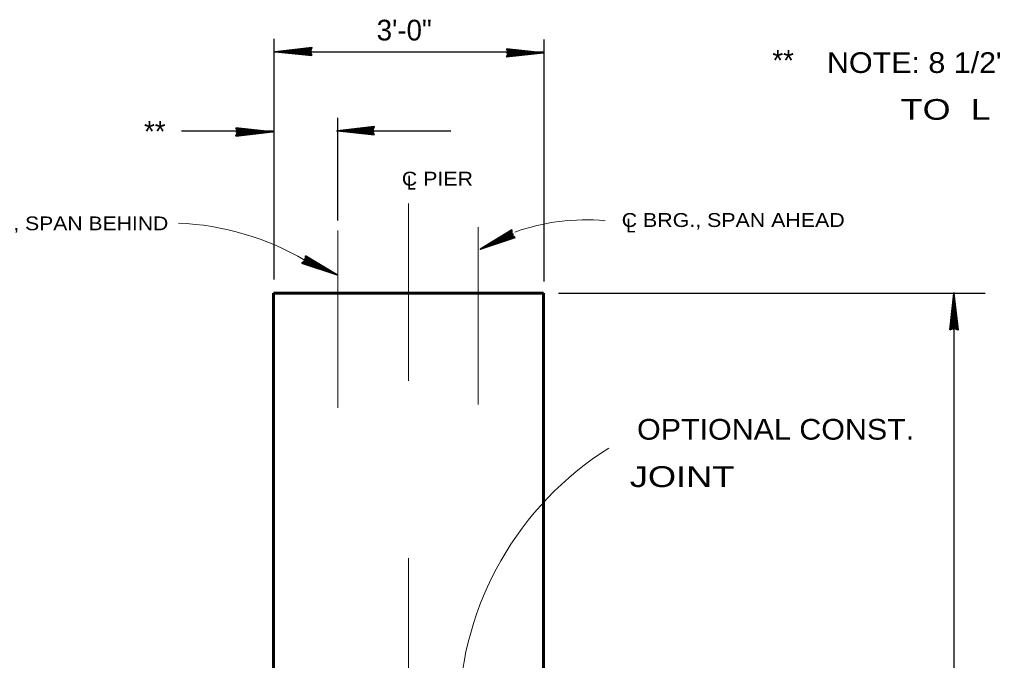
# Model space of a CAD drawing. Extents: x 1.6 to 19.9, y 2.8 to 9.5.
# Drawn here: x 17.696 to 18.245, y 8.128 to 8.49 of the extents above; entities that cross this region are included whole.
import ezdxf
from ezdxf.enums import TextEntityAlignment as Align

# ---------------------------------------------------------------- set-up
doc = ezdxf.new("R2010")
doc.units = 0
doc.header["$LTSCALE"] = 0.0047
doc.linetypes.add('DOT_DASHED', pattern=[7.7, 5, -1.2, 0.3, -1.2])
doc.layers.add('1', color=7, linetype='Continuous', lineweight=35)
doc.layers.add('5', color=7, linetype='Continuous', lineweight=13)

msp = doc.modelspace()

# ---------------------------------------------------------------- linework, layer by layer
at = {"layer": '1', "lineweight": 25}
for p, q in [((17.83975, 8.478833), (17.83975, 8.343)), ((17.992, 8.478333), (17.992, 8.34175)), ((17.839917, 8.4715), (17.991917, 8.4715)), ((17.875667, 8.43425), (17.875667, 8.37625)), ((17.787667, 8.426917), (17.839167, 8.426917)), ((17.875083, 8.426917), (17.939667, 8.426917)), ((18.2235, 8.335667), (18.2235, 7.721417)), ((18.00025, 8.33525), (18.241083, 8.33525))]:
    msp.add_line(p, q, dxfattribs=at)
at = {"layer": '1'}
for p, q in [((17.86075, 8.4735), (17.846417, 8.471917)), ((17.86075, 8.47325), (17.846417, 8.47175)), ((17.860833, 8.473083), (17.846417, 8.4715)), ((17.860833, 8.472833), (17.846417, 8.47125)), ((17.971417, 8.472833), (17.987, 8.471083)), ((17.971417, 8.47275), (17.987, 8.471)), ((17.971417, 8.472667), (17.987, 8.471)), ((17.9715, 8.472917), (17.987, 8.47125)), ((17.861167, 8.4715), (17.8405, 8.4715)), ((17.860833, 8.47), (17.845417, 8.471583)), ((17.86075, 8.46975), (17.845417, 8.471417)), ((17.86075, 8.4695), (17.845417, 8.47125)), ((17.86075, 8.4695), (17.845417, 8.47125)), ((17.86075, 8.469667), (17.845417, 8.47125)), ((17.971083, 8.470917), (17.991917, 8.470917)), ((17.971417, 8.4725), (17.987, 8.47075)), ((17.971417, 8.4695), (17.985917, 8.471083)), ((17.971417, 8.469333), (17.985917, 8.470917)), ((17.971417, 8.469083), (17.986, 8.470667)), ((17.9715, 8.468833), (17.986, 8.4705)), ((17.895917, 8.428917), (17.881583, 8.427333)), ((17.895917, 8.428667), (17.881583, 8.427167)), ((17.818333, 8.426333), (17.839167, 8.426333)), ((17.818667, 8.42825), (17.83425, 8.4265)), ((17.818667, 8.428167), (17.83425, 8.426417)), ((17.818667, 8.428083), (17.83425, 8.426417)), ((17.818667, 8.427917), (17.83425, 8.426167)), ((17.818667, 8.424917), (17.833167, 8.4265)), ((17.818667, 8.42475), (17.833167, 8.426333)), ((17.818667, 8.4245), (17.83325, 8.426083)), ((17.81875, 8.428333), (17.83425, 8.426667)), ((17.81875, 8.42425), (17.83325, 8.425917)), ((17.896333, 8.426917), (17.875667, 8.426917)), ((17.896, 8.425417), (17.880583, 8.427)), ((17.895917, 8.425167), (17.880583, 8.426833)), ((17.895917, 8.424917), (17.880583, 8.426667)), ((17.895917, 8.424917), (17.880583, 8.426667)), ((17.895917, 8.425083), (17.880583, 8.426667)), ((17.896, 8.4285), (17.881583, 8.426917)), ((17.896, 8.42825), (17.881583, 8.426667)), ((17.974917, 8.36875), (17.956167, 8.36)), ((17.973667, 8.370333), (17.961333, 8.362917)), ((17.973833, 8.37025), (17.961417, 8.362667)), ((17.973917, 8.37), (17.9615, 8.3625)), ((17.974, 8.36975), (17.961667, 8.36225)), ((17.97525, 8.36725), (17.960667, 8.36225)), ((17.975417, 8.367), (17.960667, 8.361917)), ((17.97525, 8.366917), (17.960667, 8.362)), ((17.97525, 8.366833), (17.960667, 8.361917)), ((17.975417, 8.36675), (17.96075, 8.361833)), ((17.856167, 8.3525), (17.870083, 8.347833)), ((17.856167, 8.35225), (17.869917, 8.347667)), ((17.856333, 8.35275), (17.870083, 8.348083)), ((17.856417, 8.353), (17.870167, 8.34825)), ((17.856667, 8.354333), (17.8755, 8.3455)), ((17.857667, 8.35575), (17.871083, 8.347667)), ((17.857667, 8.355583), (17.871, 8.3475)), ((17.85775, 8.356), (17.871167, 8.34775)), ((17.85775, 8.355917), (17.871167, 8.34775)), ((17.857917, 8.356), (17.871167, 8.347833)), ((18.2215, 8.315), (18.223167, 8.330333)), ((18.2215, 8.314833), (18.22325, 8.330333)), ((18.221667, 8.314833), (18.223333, 8.330333)), ((18.22175, 8.314833), (18.223417, 8.33025)), ((18.221917, 8.314833), (18.223667, 8.33025)), ((18.2235, 8.3145), (18.2235, 8.335167)), ((18.224833, 8.31475), (18.22325, 8.329167)), ((18.225083, 8.314833), (18.2235, 8.32925)), ((18.22525, 8.314833), (18.223667, 8.329333)), ((18.2255, 8.315), (18.223917, 8.329333))]:
    msp.add_line(p, q, dxfattribs=at)
at = {"layer": '1', "linetype": 'DOT_DASHED', "lineweight": 13}
for p, q in [((17.87575, 8.370583), (17.87575, 8.2)), ((17.954917, 8.372417), (17.954917, 8.195917))]:
    msp.add_line(p, q, dxfattribs=at)
at = {"layer": '1', "lineweight": 60}
for p, q in [((17.839583, 7.862833), (17.839583, 8.33525)), ((17.839583, 8.33525), (17.991833, 8.33525)), ((17.991833, 7.86225), (17.991833, 8.33525))]:
    msp.add_line(p, q, dxfattribs=at)
at = {"layer": '1'}
for points in [[(17.861167, 8.46925), (17.8405, 8.4715), (17.861167, 8.473833), (17.860167, 8.4715)], [(17.971083, 8.473167), (17.991917, 8.470917), (17.971083, 8.4685), (17.972167, 8.470917)], [(17.896333, 8.424667), (17.875667, 8.426917), (17.896333, 8.42925), (17.895333, 8.426917)], [(17.818333, 8.428583), (17.839167, 8.426333), (17.818333, 8.423917), (17.819417, 8.426333)], [(17.975917, 8.366667), (17.956167, 8.36), (17.973917, 8.370917), (17.973917, 8.36825)], [(17.857583, 8.356333), (17.8755, 8.3455), (17.855583, 8.35225), (17.857667, 8.353833)], [(18.221167, 8.3145), (18.2235, 8.335167), (18.225833, 8.3145), (18.2235, 8.315583)]]:
    msp.add_lwpolyline(points, close=True, dxfattribs=at)
for points in [[(17.859833, 8.47125), (17.850583, 8.471083), (17.850583, 8.471333), (17.852417, 8.47125), (17.859833, 8.471083), (17.853917, 8.471), (17.860083, 8.47075), (17.855667, 8.470667), (17.860167, 8.470417), (17.853167, 8.471), (17.843917, 8.471333), (17.845833, 8.471917), (17.843333, 8.471667), (17.859833, 8.47175), (17.854917, 8.472), (17.860083, 8.472), (17.8495, 8.47125), (17.860167, 8.4725), (17.85975, 8.47125), (17.860583, 8.469833), (17.860167, 8.470167), (17.85975, 8.471), (17.859167, 8.47075), (17.859583, 8.470083), (17.859917, 8.471583), (17.86025, 8.4725), (17.86075, 8.4735)], [(17.972417, 8.471083), (17.98175, 8.47125), (17.981667, 8.471), (17.979917, 8.471083), (17.972417, 8.47125), (17.9785, 8.471417), (17.97225, 8.471583), (17.9765, 8.47175), (17.972, 8.472), (17.979167, 8.471417), (17.988417, 8.471), (17.9865, 8.4705), (17.989167, 8.47075), (17.972417, 8.470667), (17.977333, 8.470333), (17.97225, 8.470333), (17.98275, 8.471), (17.972083, 8.47), (17.972583, 8.471), (17.971667, 8.4725), (17.972083, 8.47225), (17.972583, 8.471417), (17.973, 8.471667), (17.972667, 8.47225), (17.972333, 8.47075), (17.971917, 8.47), (17.9715, 8.468917)], [(17.895, 8.426667), (17.88575, 8.4265), (17.88575, 8.42675), (17.887583, 8.426667), (17.895, 8.4265), (17.889083, 8.426417), (17.89525, 8.426167), (17.890833, 8.426083), (17.895333, 8.425833), (17.888333, 8.426417), (17.879083, 8.42675), (17.881, 8.427333), (17.8785, 8.427083), (17.895, 8.427167), (17.890083, 8.427417), (17.89525, 8.427417), (17.884667, 8.426667), (17.895333, 8.427917), (17.894917, 8.426667), (17.89575, 8.42525), (17.895333, 8.425583), (17.894917, 8.426417), (17.894333, 8.426167), (17.89475, 8.4255), (17.895083, 8.427), (17.895417, 8.427917), (17.895917, 8.428917)], [(17.819667, 8.4265), (17.829, 8.426667), (17.828917, 8.426417), (17.827167, 8.4265), (17.819667, 8.426667), (17.82575, 8.426833), (17.8195, 8.427), (17.82375, 8.427167), (17.81925, 8.427417), (17.826417, 8.426833), (17.835667, 8.426417), (17.83375, 8.425917), (17.836417, 8.426167), (17.819667, 8.426083), (17.824583, 8.42575), (17.8195, 8.42575), (17.83, 8.426417), (17.819333, 8.425417), (17.819833, 8.426417), (17.818917, 8.427917), (17.819333, 8.427667), (17.819833, 8.426833), (17.82025, 8.427083), (17.819917, 8.427667), (17.819583, 8.426167), (17.819167, 8.425417), (17.81875, 8.424333)], [(17.973667, 8.368083), (17.965417, 8.364), (17.965417, 8.364083), (17.967, 8.364833), (17.973833, 8.367833), (17.968583, 8.365167), (17.974167, 8.367667), (17.97025, 8.365667), (17.974583, 8.3675), (17.967917, 8.365), (17.959333, 8.361417), (17.960917, 8.362583), (17.958667, 8.361417), (17.973583, 8.368417), (17.969, 8.366667), (17.973667, 8.368833), (17.964417, 8.363583), (17.973583, 8.369167), (17.973667, 8.367917), (17.975083, 8.367), (17.9745, 8.367), (17.973833, 8.367583), (17.9735, 8.36725), (17.974167, 8.366833), (17.973667, 8.36825), (17.973667, 8.36925), (17.973667, 8.370333)], [(17.858, 8.353917), (17.866417, 8.350167), (17.866333, 8.35), (17.864833, 8.35075), (17.858083, 8.354083), (17.863583, 8.351667), (17.858, 8.3545), (17.861917, 8.35275), (17.857917, 8.355), (17.864167, 8.351333), (17.872417, 8.347167), (17.870417, 8.3475), (17.872917, 8.346583), (17.85775, 8.3535), (17.862083, 8.35125), (17.857417, 8.35325), (17.867333, 8.3495), (17.857167, 8.353083), (17.858, 8.353833), (17.85775, 8.355583), (17.858083, 8.355083), (17.858167, 8.354167), (17.858667, 8.354167), (17.858667, 8.355), (17.857667, 8.35375), (17.857, 8.353083), (17.856167, 8.352333)], [(18.22325, 8.315917), (18.223083, 8.325083), (18.223417, 8.325), (18.22325, 8.32325), (18.223083, 8.315917), (18.222917, 8.321833), (18.22275, 8.315667), (18.222667, 8.32), (18.222417, 8.315417), (18.222917, 8.3225), (18.223417, 8.33175), (18.223917, 8.32975), (18.223667, 8.332333), (18.223667, 8.315917), (18.224, 8.32075), (18.224, 8.315667), (18.223333, 8.32625), (18.224417, 8.3155), (18.223333, 8.316), (18.221833, 8.315), (18.222167, 8.3155), (18.222917, 8.316), (18.22275, 8.316417), (18.222083, 8.316083), (18.223583, 8.31575), (18.224417, 8.315417), (18.225417, 8.315)]]:
    msp.add_lwpolyline(points, dxfattribs=at)
at = {"layer": '1', "lineweight": 13}
for centre, radius, start, end in [((18.01561, 8.258539), 0.118072, 84.66253, 109.74805), ((18.124414, 8.095025), 0.180294, 122.06338, 178.61588)]:
    msp.add_arc(centre, radius, start, end, dxfattribs=at)
at = {"layer": '5', "linetype": 'DOT_DASHED'}
msp.add_line((17.91575, 8.38575), (17.91575, 8.03225), dxfattribs=at)
at = {"layer": '5'}
msp.add_arc((17.779249, 8.21983), 0.155087, 59.71776, 87.51672, dxfattribs=at)

# ---------------------------------------------------------------- texts
at = {"layer": '1'}
msp.add_text('3\'-0"', height=0.01167, dxfattribs=at).set_placement((17.89775, 8.477833))
for p in [(18.133167, 8.46075), (17.778583, 8.420667)]:
    msp.add_text('**', height=0.01167, dxfattribs=at).set_placement(p, align=Align.RIGHT)
for s, width, p in [('NOTE: 8 1/2" MIN. FROM EDGE OF PIER', 1.1, (18.4765, 8.4595)), ('  TO  L BEARING TYPICAL.', 1.3, (18.436917, 8.433083)), ('OPTIONAL CONST.', 1.1, (18.201083, 8.252583))]:
    msp.add_text(s, height=0.01167, dxfattribs=dict(at, width=width)).set_placement(p, align=Align.RIGHT)
for s, height, width, p in [('C PIER', 0.007833, 1.15, (17.911917, 8.395917)), ('L', 0.007833, 0.85, (17.914917, 8.393667)), ('C BRG., SPAN AHEAD', 0.007833, 1.15, (18.036, 8.372583)), ('C BRG., SPAN BEHIND', 0.00775, 1.15, (17.651667, 8.37075)), ('L', 0.007833, 0.9, (18.038667, 8.3695)), ('JOINT   ', 0.01175, 1.3, (18.040583, 8.225833))]:
    msp.add_text(s, height=height, dxfattribs=dict(at, width=width)).set_placement(p)

doc.saveas('drawing.dxf')
